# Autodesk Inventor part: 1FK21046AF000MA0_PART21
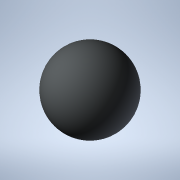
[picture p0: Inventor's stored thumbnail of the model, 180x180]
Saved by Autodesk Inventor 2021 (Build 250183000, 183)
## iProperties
Created: 2025-04
Part Number: 1FK21046AF000MA0_PART21
Material: Generic
Catalog Web Link: www.3dfindit.com
Description: -Servo synchronous motor
Document SubType Name: Modeling
Designer: psAdmin
Mass: 0.137258 g
Surface Area: 1.2868 cm^2
Volume: 0.137258 cm^3
Density: 1 g/cm^3
Appearance: PSOLRGB-212-217-219
Category: PARTsolutions
Title: 1FK21046AF000MA0_PART21
Author: Cadenas PARTsolutions
Comments: Servo synchronous motor
Sending System: PARTsolutions
Preprocessor: ST-DEVELOPER v19.3
PSOL_IDENT_0: {$CADENAS_DATA/23d-libs/siemens_ag/_cat_/1c/1f/1fk21046af000ma0.prj},216 {VTYP=3D},{NB=1FK21046AF000
PSOL_IDENT_1: MA0_PART21},{LINA=1FK21046AF000MA0_PART21},{NN=1FK21046AF000MA0_PART21},{NOPRJ=TRUE},{DATE=19.08.202
PSOL_IDENT_2: 5 14:00:28},{GEOMDATE=30.07.2025 02:02:08},{VERSION=},{LINEID=10},{WBVAR=},{WBNUMERIC=}  {NB=1FK2104
PSOL_IDENT_3: 6AF000MA0_PART21},{LINA=1FK21046AF000MA0_PART21},{KT=DUMMY},{PREVIEW=../../../_pool_/cb/72/p_d211_xx
PSOL_IDENT_4: _00434j.png},{DESCSHORT=SIMOTICS S-1FK2 HD, SINAMICS S210 3AC 400V-480V, 3.2 Nm, 3000 rpm},{DESCLONG=
PSOL_IDENT_5: SIMOTICS S-1FK2 HD servo motor M0=3.2 Nm; PN = 1 kW at nN=3000 rpm (380-480 V); PN = 0.5 kW at nN=15
PSOL_IDENT_6: 00 rpm (200-240 V); degree of protection IP64; cylindrical shaft D19x40mm; absolute encoder 22-bit +
PSOL_IDENT_7: 12-bit multiturn (encoder AM22DQC); with OCC interface; plug size M17, rotatable; SIMOTICS S-1FK2 s
PSOL_IDENT_8: ervomotorfor a wide range of uses in industrial environments. SIMOTICS S‑1FK2 servomotors are compac
PSOL_IDENT_9: t synchronous motors with a high dynamic performance that set themselves apart as a result of their
PSOL_IDENT_10: high power density, degree of protection and overload capability. The motors are available in two va
PSOL_IDENT_11: riants: as High Dynamic variant (highest dynamic performance as a result of the low intrinsic moment
PSOL_IDENT_12: of inertia for applications demanding a high dynamic performance with low moved masses) - and as Co
PSOL_IDENT_13: mpact variant (precise and stable closed-loop control for medium up to large moved masses as a resul
PSOL_IDENT_14: t of a medium intrinsic moment of inertia). SIMOTICSS‑1FK2 servomotors fully exploit their strengths
PSOL_IDENT_15: in a system with the SINAMICSS210 frequency converter and simple connection using the one cable con
PSOL_IDENT_16: nection (OCC). Advantages include the short control and positioning times, fast and precise correcti
PSOL_IDENT_17: on of disturbing quantities as well as stable control with a high dynamic performance. The servo mot
PSOL_IDENT_18: ors can be configured to address a wide range of requirements. For example with and without holding
PSOL_IDENT_19: brake, IP64 or IP65 degree of protection, singleturn or multiturn absolute encoders - to name just a
PSOL_IDENT_20: few. Further, the servomotors are available in different shaft heights extending from 20 to 100. A
PSOL_IDENT_21: shaft sealing ring is available to achieve an IP65 degree of protection and for subsequent mounting
PSOL_IDENT_22: at the motor or as spare part. SIMOTICS - the optimum motor for each and every motion control applic
PSOL_IDENT_23: ation.},{INTNO=195125049666},{SUPPLIERALTNO=1FK2104-6AF00-0MA0},{MANUID=1FK21046AF000MA0},{MANUNAME=
PSOL_IDENT_24: Siemens},{MANUTYPEDESC=Synchronous motor 1FK2-HD 3.2 NM},{AAU732=SIMOTICS},{AAO057=S-1FK2},{AAU734=S
PSOL_IDENT_25: IMOTICS S-1FK2 HD servo motor M0=3.2 Nm; PN = 1 kW at nN=3000 rpm (380-480 V); PN = 0.5 kW at nN=150
PSOL_IDENT_26: 0 rpm (200-240 V); degree of protection IP64; cylindrical shaft D19x40mm; absolute encoder 22-bit +
PSOL_IDENT_27: 12-bit multiturn (encoder AM22DQC); with OCC interface; plug size M17, rotatable;},{AAW338=Synchrono
PSOL_IDENT_28: us motor 1FK2-HD 3.2 NM},{AAO742=SIMOTICS},{AAO663=4042948694374},{NOCUPEROU=1},{PRICEQUANTITY=1},{Q
PSOL_IDENT_29: UANTITYMIN=1},{QUANTITYINT=1},{CTN=85015220},{COO=DE},{AAO676=1FK2104-6AF00-0MA0},{AAO677=Siemens AG
PSOL_IDENT_30: },{ORDERUNIT=C62},{CONTENTUNIT=C62}
NB: 1FK21046AF000MA0_PART21
NT: Servo synchronous motor
NBSYN: $MANUID._PART21
LINA: 1FK21046AF000MA0_PART21
CATALOG: SIEMENS
PREVIEW: ../../../_pool_/cb/72/p_d211_xx_00434j.png
DESCSHORT: SIMOTICS S-1FK2 HD, SINAMICS S210 3AC 400V-480V, 3.2 Nm, 3000 rpm
DESCLONG: SIMOTICS S-1FK2 HD servo motor M0=3.2 Nm; PN = 1 kW at nN=3000 rpm (380-480 V); PN = 0.5 kW at nN=1500 rpm (200-240 V); degree of protection IP64; cylindrical s
INTNO: 195125049666
SUPPLIERALTNO: 1FK2104-6AF00-0MA0
MANUID: 1FK21046AF000MA0
MANUNAME: Siemens
MANUTYPEDESC: Synchronous motor 1FK2-HD 3.2 NM
AAU732: SIMOTICS
AAO057: S-1FK2
AAU734: SIMOTICS S-1FK2 HD servo motor M0=3.2 Nm; PN = 1 kW at nN=3000 rpm (380-480 V); PN = 0.5 kW at nN=1500 rpm (200-240 V); degree of protection IP64; cylindrical s
AAW338: Synchronous motor 1FK2-HD 3.2 NM
AAO742: SIMOTICS
AAO663: 4042948694374.0
NOCUPEROU: 1
PRICEQUANTITY: 1
QUANTITYMIN: 1
QUANTITYINT: 1
CTN: 85015220
COO: DE
ARTICLENO: 1FK21046AF000MA0_PART21
BOMINFO: 1FK21046AF000MA0_PART21
CREATOR: CADENAS GmbH
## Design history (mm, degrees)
feature "2025_04_17_15_39_11_0412"
body "Solid1"
